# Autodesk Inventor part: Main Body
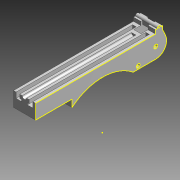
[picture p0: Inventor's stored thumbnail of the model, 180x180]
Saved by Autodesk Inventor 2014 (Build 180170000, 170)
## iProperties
Created: 2013-11
Part Number: Main Body
Material: Generic
Document SubType Name: Modeling
Designer: 603839
Density: 1 g/cm^3
Appearance: Smooth - White
Mass: 205.48 g
Surface Area: 490.982 cm^2
Volume: 205.48 cm^3
Author: 603839
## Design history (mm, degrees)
sketch "Sketch1"
  geometry: L1 (-19.05, 114.3)-(-19.05, -114.3); L2 (-19.05, -114.3)-(19.05, -114.3); L3 (19.05, -114.3)-(19.05, 114.3); L4 (19.05, 114.3)-(-19.05, 114.3); L5 (-19.05, 114.3)-(19.05, -114.3); L6 (-19.05, -114.3)-(19.05, 114.3); 1 further point
  constraints: 12 end point, 2 midpoint, 2 parallel, 1 perpendicular, 1 vertical
  dimensions: "d0" = 228.6 distance of L1.start L1.end; "d1" = 38.1 distance of L2.end L1.end
extrude "Extrusion1" new body sketch "Sketch1" distance "d2" = 38.1; taper "d3" = 0 deg
sketch "Sketch2"
  geometry: L1 (0, 38.1)-(38.1, 38.1) reference; C1 r 3.81 at (19.05, 38.1); 1 further point
  constraints: 1 centre point, 1 midpoint
  dimensions: "d4" = 7.62 diameter of C1
extrude "Extrusion2" cut sketch "Sketch2" distance "d5" = 190.5; taper "d6" = 0 deg
sketch "Sketch3"
  geometry: L1 (114.3, -19.05)-(114.3, 19.05) reference; L2 (114.3, 19.05)-(-114.3, 19.05) reference; L3 (95.25, 19.05)-(95.25, -19.05); L4 (95.25, 19.05)-(133.35, 19.05); L5 (95.25, 19.05)-(114.3, 19.05); L6 (114.3, 0)-(114.3, 19.05); L7 (95.25, -19.05)-(114.3, -19.05); L8 (114.3, -19.05)-(114.3, 0); A1 r 19.05 centre (95.25, 0) between (95.25, -19.05) and (95.25, 19.05); 1 further point
  constraints: 12 end point, 3 point on circle, 2 tangent, 1 centre point, 1 collinear, 1 horizontal, 1 perpendicular, 1 point on line
  dimensions: "d9" = 38.1 distance of L3.start L3.end; "d10" = 90 deg angle of L3 L4
extrude "Extrusion3" cut sketch "Sketch3" distance "d11" = 203.2; taper "d12" = 0 deg
hole "Hole1" diameter "d15" = 6.604; stored, may be unused: countersink angle "d19" = 82 deg, drill point angle "d21" = 0 deg; dims "d16" = 19.05, "d17" = 9.525, "d18" = 6.35, "d20" = 38.1, "d65" = 25.4, "d66" = 25.4
sketch "Sketch4"
  geometry: L1 (-114.3, -19.05)-(95.25, -19.05) reference; L2 (-114.3, -19.05)-(-50.8, -19.05); L3 (95.25, -19.05)-(82.55, -19.05); A1 r 19.05 centre (95.25, 0) between (95.25, -19.05) and (95.25, 19.05) reference; A2 r 126.201 centre (15.875, -126.2) between (82.55, -19.05) and (-50.8, -19.05); 1 further point
  constraints: 4 end point, 3 point on circle, 2 point on line, 1 centre point
  dimensions: "d24" = 63.5 distance of L1.start L2.end; "d25" = 12.7 distance of L3.start L3.end
extrude "Extrusion4" cut sketch "Sketch4" distance "d26" = 203.2; taper "d27" = 0 deg
sketch "Sketch5"
  geometry: L1 (-114.3, 19.05)-(-114.3, -19.05) reference; L2 (-114.3, -19.05)-(-50.8, -19.05) reference; L3 (-114.3, -19.05)-(-114.3, -6.35); L4 (-114.3, -6.35)-(-50.8, -6.35); L5 (-50.8, -6.35)-(-50.8, -19.05); 1 further point
  constraints: 6 end point, 1 parallel, 1 perpendicular, 1 point on line
  dimensions: "d28" = 12.7 distance of L1.end L3.end
extrude "Extrusion5" cut sketch "Sketch5" distance "d29" = 203.2; taper "d30" = 0 deg
workplane "Work Plane1"
sketch "Sketch10"
  geometry: L1 (0, 12.7)-(0, 0) reference; L2 (12.446, 12.7)-(12.446, -25.4); L3 (12.446, -25.4)-(25.146, -25.4); L4 (25.146, -25.4)-(25.146, 12.7); L5 (25.146, 12.7)-(12.446, 12.7); 1 further point
  constraints: 8 end point, 3 parallel, 1 perpendicular
  dimensions: "d47" = 38.1 distance of L2.start L2.end; "d50" = 12.7 distance of L2.end L3.end
extrude "Extrusion8" cut sketch "Sketch10" distance "d48" = 38.1; taper "d49" = 0 deg
sketch "Sketch11"
  geometry: L1 (-2.794, 196.85)-(-2.794, 209.55) reference; L2 (22.86, 209.55)-(22.86, 0) reference; L3 (-15.24, 209.55)-(-2.794, 209.55); L4 (-2.794, 209.55)-(-2.794, 204.476); L5 (-2.794, 204.476)-(-15.24, 204.476); L6 (-15.24, 204.476)-(-15.24, 209.55); L7 (9.906, 209.55)-(22.86, 209.55); L8 (22.86, 209.55)-(22.86, 204.476); L9 (22.86, 204.476)-(9.906, 204.476); L10 (9.906, 204.476)-(9.906, 209.55); 1 further point
  constraints: 16 end point, 4 parallel, 2 horizontal, 2 perpendicular, 2 point on line
extrude "Extrusion9" join sketch "Sketch11" distance "d51" = 12.7; taper "d52" = 0 deg
sketch "Sketch12"
  geometry: L1 (95.25, 19.05)-(95.25, 31.75) reference; A1 r 19.05 centre (95.25, 0) between (95.25, -19.05) and (95.25, 19.05) reference; A2 r 23.785 centre (85.449, 10.078) between (109.035, 13.148) and (95.25, 31.75); 1 further point
  constraints: 3 point on circle, 1 centre point
extrude "Extrusion10" join sketch "Sketch12" distance "d53" = 38.1; taper "d54" = 0 deg
sketch "Sketch13"
  geometry: L1 (12.7, -12.7)-(12.7, 0) reference; L2 (12.7, 0)-(0, 0) reference; L3 (0, -12.7)-(0, 0) reference; L4 (12.7, -12.7)-(0, -12.7) reference; 1 further point
extrude "Extrusion11" cut sketch "Sketch13" distance "d55" = 38.1; taper "d56" = 0 deg
sketch "Sketch14"
  geometry: L1 (0, -12.227)-(12.7, -12.227); L2 (12.7, -12.227)-(12.7, 6.703); L3 (12.7, 6.703)-(0, 6.703); L4 (0, 6.703)-(0, -12.227); 1 further point
  constraints: 8 end point, 2 parallel, 1 horizontal, 1 perpendicular
extrude "Extrusion12" cut sketch "Sketch14" distance "d57" = 38.1; taper "d58" = 0 deg
sketch "Sketch15"
  geometry: L1 (12.7, 0)-(12.7, 38.1) reference; L2 (0, 0)-(0, 38.1) reference; L3 (0, 0)-(0, 6.35); L4 (0, 6.35)-(0, 29.21); L5 (0, 29.21)-(12.7, 29.21); L6 (12.7, 29.21)-(12.7, 6.35); L7 (12.7, 6.35)-(0, 6.35); L8 (0, 6.35)-(0, 29.21); 1 further point
  constraints: 12 end point, 3 point on line, 2 parallel, 1 horizontal, 1 perpendicular
  dimensions: "d59" = 6.35 distance of L2.start L3.end; "d60" = 22.86 distance of L3.end L4.end
extrude "Extrusion13" cut sketch "Sketch15" distance "d61" = 12.7; taper "d62" = 0 deg
sketch "Sketch16"
  geometry: L1 (12.7, -11.499)-(0, -11.499) reference; L2 (12.7, 0)-(12.7, -11.499) reference; L3 (0, 0)-(12.7, 0) reference; L4 (0, 0)-(0, -11.499) reference; 1 further point
extrude "Extrusion14" cut sketch "Sketch16" distance "d63" = 12.7; taper "d64" = 0 deg
hole "Hole2" diameter "d69" = 6.604; stored, may be unused: countersink angle "d73" = 82 deg, drill point angle "d75" = 0 deg; dims "d67" = 7.62, "d68" = 5.08, "d70" = 19.05, "d71" = 9.525, "d72" = 6.35, "d74" = 38.1
sketch "Sketch7"
  geometry: L1 (-19.05, 0)-(-3.81, 0) reference; L2 (-19.05, -25.4)-(19.05, -25.4) reference; L3 (0, 0)-(0, -25.4); L4 (-11.43, 0)-(-8.255, 0); L5 (-11.43, 0)-(-14.605, 0); L6 (-14.605, 0)-(-14.605, -6.35); L7 (-8.255, 0)-(-8.255, -6.35); L8 (-8.255, -9.525)-(-17.78, -9.525); L9 (-17.78, -9.525)-(-17.78, -6.35); L10 (-17.78, -6.35)-(-14.605, -6.35); L11 (8.255, 0)-(8.255, -6.35); L12 (11.43, 0)-(8.255, 0); L13 (17.78, -9.525)-(17.78, -6.35); L14 (8.255, -9.525)-(17.78, -9.525); L15 (17.78, -6.35)-(14.605, -6.35); L16 (14.605, 0)-(14.605, -6.35); L17 (11.43, 0)-(14.605, 0); L18 (-8.255, -6.35)-(-8.255, -9.525); L19 (8.255, -6.35)-(8.255, -9.525); A1 r 3.81 centre (0, 0) between (-3.81, 0) and (3.81, 0) reference; 3 further points
  constraints: 34 end point, 8 symmetric about line, 3 perpendicular, 2 midpoint, 2 point on line, 1 parallel
  dimensions: "d78" = 3.175 distance of L4.start L5.end; "d81" = 12.7 distance of point (-5.08, -9.525) L8.end; "d82" = 3.175 distance of L8.end L9.end
extrude "Extrusion15" cut sketch "Sketch7" distance "d83" = 203.2; taper "d84" = 0 deg
sketch "Sketch17"
  geometry: L1 (90.176, 31.75)-(95.25, 31.75) reference; L2 (90.176, 19.05)-(90.176, 31.75) reference; L3 (-114.3, 19.05)-(-114.3, -6.35) reference; L4 (90.176, 19.05)-(107.477, 19.05); C1 r 3.302 at (95.256, 24.13) reference; A1 r 23.785 centre (85.449, 10.078) between (109.035, 13.148) and (95.25, 31.75) reference; 1 further point
  constraints: 2 end point, 1 perpendicular, 1 point on circle
extrude "Extrusion16" cut sketch "Sketch17" distance "d85" = 203.2; taper "d86" = 0 deg
sketch "Sketch18"
  geometry: L1 (107.477, 19.05)-(-114.3, 19.05) reference; L2 (82.55, -19.05)-(95.25, -19.05) reference; L3 (107.477, 19.05)-(107.477, 31.75); L4 (107.477, 31.75)-(94.777, 31.75); L5 (94.777, 31.75)-(94.777, 19.05); 1 further point
  constraints: 6 end point, 3 perpendicular, 1 point on line
  dimensions: "d87" = 12.7 distance of L1.start L3.end; "d88" = 12.7 distance of L3.end L4.end
extrude "Extrusion17" join sketch "Sketch18" stored distance "d89" = 203.2; taper "d90" = 0 deg
sketch "Sketch19"
  geometry: L1 (-12.954, 0)-(-25.654, 0) reference; L2 (0, 12.7)-(-38.1, 12.7) reference; L3 (-25.654, 0)-(-25.654, 12.7); L4 (-12.954, 0)-(-12.954, 12.7); 1 further point
  constraints: 4 end point, 2 perpendicular, 2 point on line
extrude "Extrusion18" cut sketch "Sketch19" distance "d91" = 203.2; taper "d92" = 0 deg
sketch "Sketch20"
  geometry: L1 (107.477, 19.05)-(107.477, 31.75) reference; L2 (107.477, 31.75)-(94.777, 31.75) reference; L3 (94.777, 31.75)-(94.777, 19.05) reference; L4 (107.477, 19.05)-(112.569, 7.934); L5 (107.477, 19.05)-(107.477, 25.4); L6 (94.777, 25.4)-(107.477, 25.4); A1 r 19.05 centre (95.25, 0) between (95.25, -19.05) and (109.035, 13.148) reference; 1 further point
  constraints: 6 end point, 2 midpoint, 1 perpendicular, 1 point on circle, 1 tangent
extrude "Extrusion19" cut sketch "Sketch20" distance "d93" = 203.2; taper "d94" = 0 deg
sketch "Sketch21"
  geometry: L1 (107.477, 19.05)-(112.569, 7.934); A1 r 19.05 centre (95.25, 0) between (95.25, -19.05) and (109.035, 13.148) reference; A2 r 23.785 centre (85.449, 10.078) between (109.035, 13.148) and (107.477, 19.05) reference; 1 further point
  constraints: 2 end point, 1 point on circle, 1 tangent
extrude "Extrusion20" join sketch "Sketch21" stored distance "d95" = 203.2; taper "d96" = 0 deg
sketch "Sketch22"
  geometry: L1 (12.954, 0)-(25.654, 0); L2 (25.654, 0)-(25.654, -12.227); L3 (25.654, -12.227)-(12.954, -12.227); L4 (12.954, -12.227)-(12.954, 0); 1 further point
  constraints: 8 end point, 2 parallel, 1 horizontal, 1 perpendicular
extrude "Extrusion21" cut sketch "Sketch22" distance "d97" = 2.54; taper "d98" = 0 deg
sketch "Sketch23"
  geometry: L1 (107.477, 25.4)-(94.777, 25.4) reference; C1 r 3.175 at (101.127, 25.4); 1 further point
  constraints: 1 centre point, 1 midpoint
  dimensions: "d99" = 6.35 diameter of C1
extrude "Extrusion22" join sketch "Sketch23" stored distance "d100" = 2.54; taper "d101" = 0 deg
sketch "Sketch25"
  geometry: L1 (94.777, 19.05)-(-114.3, 19.05) reference; L2 (107.477, 25.4)-(104.302, 25.4) reference; L3 (64.328, 19.05)-(64.328, 12.923); L4 (107.477, 19.05)-(107.477, 25.4) reference; L5 (77.028, 10.383)-(64.328, 10.383); L6 (64.328, 10.383)-(64.328, 12.923); C1 r 3.175 at (64.328, 12.923); 1 further point
  constraints: 6 end point, 2 perpendicular, 2 point on line, 1 centre point, 1 coincident
  dimensions: "d105" = 6.35 diameter of C1; "d108" = 12.7 distance of L5.start L5.end; "d109" = 2.54 distance of L5.end L6.end
extrude "Extrusion24" join sketch "Sketch25" distance "d106" = 6.35; taper "d107" = 0 deg
sketch "Sketch26"
  geometry: C1 r 3.175 at (0, 0) reference; 1 further point
extrude "Extrusion25" join sketch "Sketch26" distance "d110" = 12.7; taper "d111" = 0 deg
sketch "Sketch27"
  geometry: L1 (24.927, 44.45)-(21.752, 44.45) reference; L2 (21.752, 44.45)-(21.752, 38.1); L3 (21.752, 38.1)-(15.402, 38.1); L4 (15.402, 38.1)-(15.402, 44.45); A1 r 3.175 centre (18.577, 44.45) between (15.402, 44.45) and (21.752, 44.45) reference; 1 further point
  constraints: 6 end point, 2 perpendicular, 1 tangent
  dimensions: "d112" = 6.35 distance of L1.end L2.end; "d113" = 6.35 distance of L2.end L3.end
extrude "Extrusion26" join sketch "Sketch27" distance "d114" = 25.4; taper "d115" = 0 deg
sketch "Sketch28"
  geometry: L1 (107.477, 25.4)-(104.302, 25.4) reference; L2 (31.75, 0)-(44.45, 0); L3 (44.45, 0)-(44.45, -3.277); L4 (31.75, 0)-(31.75, -1.002); A1 r 126.201 centre (15.875, -126.2) between (82.55, -19.05) and (-50.8, -19.05) reference; A2 r 126.201 centre (15.875, -126.2) between (44.45, -3.277) and (31.75, -1.002); 1 further point
  constraints: 6 end point, 4 point on circle, 2 parallel, 1 centre point, 1 concentric, 1 perpendicular
  dimensions: "d116" = 12.7 distance of L2.start L2.end
extrude "Extrusion27" join sketch "Sketch28" distance "d117" = 12.7; taper "d118" = 0 deg
sketch "Sketch29"
  geometry: L1 (44.45, 0)-(31.75, 0) reference; L2 (31.75, 0)-(31.75, -6.35); L3 (31.75, -6.35)-(44.45, -6.35); L4 (44.45, -6.35)-(44.45, 0); 1 further point
  constraints: 6 end point, 2 perpendicular
  dimensions: "d119" = 6.35 distance of L1.end L2.end; "d120" = 12.7 distance of L2.end L3.end
extrude "Extrusion28" join sketch "Sketch29" stored distance "d121" = 12.7; taper "d122" = 0 deg
sketch "Sketch30"
  geometry: L1 (-44.45, -3.277)-(-44.45, -6.35) reference; L2 (-44.45, -6.35)-(-31.75, -6.35) reference; L3 (-44.45, -3.277)-(-44.45, -6.35); L4 (-31.75, -6.35)-(-44.45, -6.35); A1 r 126.201 centre (-15.875, -126.2) between (-44.45, -3.277) and (-82.55, -19.05) reference; A2 r 107.95 centre (-31.75, -114.3) between (-31.75, -6.35) and (-82.55, -19.05); A3 r 126.201 centre (-15.875, -126.2) between (-44.45, -3.277) and (-82.55, -19.05); 1 further point
  constraints: 4 end point, 4 point on circle, 2 centre point, 2 collinear, 2 tangent, 1 concentric
extrude "Extrusion29" join sketch "Sketch30" stored distance "d123" = 12.7; taper "d124" = 0 deg
sketch "Sketch31"
  geometry: L1 (-31.75, -6.35)-(-31.75, -1.002) reference; A1 r 126.201 centre (-15.875, -126.2) between (50.8, -19.05) and (-31.75, -1.002) reference; A2 r 267.228 centre (-30.61, -273.576) between (50.8, -19.05) and (-31.75, -6.35); 1 further point
  constraints: 2 point on circle, 1 centre point
extrude "Extrusion30" join sketch "Sketch31" stored distance "d125" = 12.7; taper "d126" = 0 deg
sketch "Sketch33"
  geometry: L1 (44.45, -6.35)-(44.45, 0) reference; L2 (44.45, 0)-(31.75, 0) reference; L3 (44.45, -3.175)-(31.75, 0); 1 further point
  constraints: 2 end point, 1 midpoint
extrude "Extrusion32" cut sketch "Sketch33" stored distance "d133" = 3.175; taper "d134" = 0 deg
sketch "Sketch34"
  geometry: C1 r 5.715 at (6.35, 6.545); 1 further point
  constraints: 1 centre point
  dimensions: "d135" = 11.43 diameter of C1
extrude "Extrusion33" cut sketch "Sketch34" distance "d136" = 3.175; taper "d137" = 0 deg
sketch "Sketch36"
  geometry: L1 (31.75, -6.35)-(44.45, -6.35) reference; L2 (31.75, -6.35)-(31.75, 0) reference; L3 (31.75, -6.35)-(44.45, -6.35); L4 (44.45, -6.35)-(44.45, -7.1); A1 r 107.95 centre (31.75, -114.3) between (82.55, -19.05) and (31.75, -6.35) reference; A2 r 107.95 centre (31.75, -114.3) between (44.45, -7.1) and (31.75, -6.35); 1 further point
  constraints: 4 end point, 3 point on circle, 2 perpendicular, 1 centre point, 1 concentric, 1 tangent
extrude "Extrusion34" join sketch "Sketch36" stored distance "d138" = 25.4; taper "d139" = 0 deg
sketch "Sketch37"
  geometry: L1 (44.45, -3.175)-(44.45, -7.1) reference; L2 (31.75, -6.35)-(31.75, 0) reference; L3 (44.45, -3.175)-(31.75, 0) reference; L4 (-50.8, -19.05)-(82.55, -19.05); A1 r 107.95 centre (31.75, -114.3) between (82.55, -19.05) and (44.45, -7.1) reference; A2 r 267.228 centre (30.61, -273.576) between (31.75, -6.35) and (-50.8, -19.05) reference; 1 further point
  constraints: 2 end point, 1 perpendicular
extrude "Extrusion35" join sketch "Sketch37" stored distance "d140" = 25.4; taper "d141" = 0 deg
sketch "Sketch38"
  geometry: L1 (44.45, -3.175)-(31.75, 0) reference; L2 (31.75, 0)-(31.75, -6.35) reference; L3 (44.45, -7.1)-(44.45, -3.175) reference; A1 r 107.95 centre (31.75, -114.3) between (44.45, -7.1) and (31.75, -6.35) reference; 1 further point
extrude "Extrusion36" cut sketch "Sketch38" stored distance "d142" = 25.4; taper "d143" = 0 deg
sketch "Sketch39"
  geometry: C1 r 3.175 at (0, 0) reference; 1 further point
extrude "Extrusion37" cut sketch "Sketch39" stored distance "d144" = 25.4; taper "d145" = 0 deg
sketch "Sketch40"
  geometry: L1 (-50.8, -19.05)-(95.25, -19.05) reference; L2 (-50.8, -6.35)-(-50.8, -19.05) reference; C1 r 3.302 at (64.77, -13.97); 1 further point
  constraints: 1 centre point
  dimensions: "d146" = 6.604 diameter of C1; "d147" = 5.08 distance from line of L1 C1.centre; "d148" = 115.57 distance from line of L2 C1.centre
extrude "Extrusion38" cut sketch "Sketch40" distance "d149" = 25.4; taper "d150" = 0 deg
sketch "Sketch41"
  geometry: L1 (-50.8, -19.05)-(95.25, -19.05) reference; A1 r 84.07 centre (2.54, -84.032) between (55.88, -19.05) and (-50.8, -19.05); 1 further point
  constraints: 3 point on circle, 1 centre point, 1 point on line
  dimensions: "d151" = 106.68 distance of L1.start A1.start
extrude "Extrusion39" cut sketch "Sketch41" stored distance "d152" = 25.4; taper "d153" = 0 deg
sketch "Sketch42"
  geometry: L1 (8.255, -9.525)-(8.255, 0) reference; L2 (-8.255, 0)-(-8.255, -9.525) reference; L3 (-17.78, -6.35)-(-14.605, -6.35) reference; L4 (-8.255, -6.35)-(-5.08, -6.35); L5 (-5.08, -6.35)-(-5.08, -9.525); L6 (-5.08, -9.525)-(-8.255, -9.525); L7 (8.255, -9.525)-(5.08, -9.525); L8 (5.08, -9.525)-(5.08, -6.35); L9 (5.08, -6.35)-(8.255, -6.35); 1 further point
  constraints: 12 end point, 3 equal length, 3 perpendicular, 2 point on line
  dimensions: "d154" = 3.175 distance of L4.start L4.end; "d155" = 3.175 distance of L4.end L5.end; "d156" = 3.175 distance of L1.start L7.end; "d157" = 3.175 distance of L7.end L8.end
extrude "Extrusion40" cut sketch "Sketch42" stored distance "d158" = 25.4; taper "d159" = 0 deg
sketch "Sketch43"
  geometry: L1 (-5.08, -9.525)-(-17.78, -9.525) reference; L2 (-17.78, -9.525)-(-17.78, -6.35) reference; L3 (-17.78, -6.35)-(-14.605, -6.35) reference; L4 (14.605, -6.35)-(17.78, -6.35) reference; L5 (17.78, -6.35)-(17.78, -9.525) reference; L6 (17.78, -9.525)-(5.08, -9.525) reference; L7 (-14.605, -6.35)-(-14.605, -9.525); L8 (14.605, -6.35)-(14.605, -9.525); 1 further point
  constraints: 4 end point, 2 perpendicular, 2 point on line
extrude "Extrusion41" join sketch "Sketch43" stored distance "d160" = 25.4; taper "d161" = 0 deg
sketch "Sketch46"
  geometry: L1 (12.7, 3.175)-(19.05, 3.175) reference; L2 (19.05, 3.175)-(19.05, 0) reference; L3 (19.05, 0)-(0, 0) reference; L4 (0, 0)-(0, -21.649) reference; L5 (25.4, -28.575)-(12.7, -28.575) reference; L6 (37.627, 9.525)-(42.719, -1.591) reference; L7 (37.627, 15.875)-(37.627, 9.525) reference; L8 (37.627, 15.875)-(34.452, 15.875) reference; L9 (34.452, 15.875)-(34.452, 9.525) reference; L10 (34.452, 9.525)-(28.102, 9.525) reference; L11 (28.102, 9.525)-(28.102, 15.875) reference; L12 (28.102, 15.875)-(24.927, 15.875) reference; L13 (24.927, 9.525)-(24.927, 15.875) reference; L14 (12.7, 9.525)-(24.927, 9.525) reference; L15 (12.7, 3.175)-(12.7, 9.525) reference; C1 r 3.302 at (25.4, -9.525) reference; A1 r 126.201 centre (-53.975, -135.725) between (12.7, -28.575) and (0, -21.649) reference; A2 r 19.05 centre (25.4, -9.525) between (25.4, -28.575) and (42.719, -1.591) reference; 1 further point
extrude "Extrusion44" join sketch "Sketch46" distance "d166" = 0.254; taper "d167" = 0 deg
sketch "Sketch47"
  geometry: L1 (0, 3.175)-(6.35, 3.175) reference; L2 (6.35, 3.175)-(6.35, 9.525) reference; L3 (-5.877, 9.525)-(6.35, 9.525) reference; L4 (-5.877, 15.875)-(-5.877, 9.525) reference; L5 (-5.877, 15.875)-(-9.052, 15.875) reference; L6 (-9.052, 15.875)-(-9.052, 9.525) reference; L7 (-9.052, 9.525)-(-15.402, 9.525) reference; L8 (-15.402, 9.525)-(-15.402, 15.875) reference; L9 (-15.402, 15.875)-(-18.577, 15.875) reference; L10 (-18.577, 9.525)-(-18.577, 15.875) reference; L11 (-23.669, -1.591)-(-18.577, 9.525) reference; L12 (6.35, -28.575)-(-6.35, -28.575) reference; L13 (19.05, -21.649)-(19.05, 0) reference; L14 (19.05, 0)-(0, 0) reference; L15 (0, 0)-(0, 3.175) reference; C1 r 3.302 at (-6.35, -9.525) reference; A1 r 19.05 centre (-6.35, -9.525) between (-23.669, -1.591) and (-6.35, -28.575) reference; A2 r 126.201 centre (73.025, -135.725) between (19.05, -21.649) and (6.35, -28.575) reference; 1 further point
extrude "Extrusion45" cut sketch "Sketch47" distance "d168" = 0.254; taper "d169" = 0 deg
sketch "Sketch51"
  geometry: L1 (55.88, -19.05)-(95.25, -19.05) reference; L2 (112.569, 7.934)-(107.477, 19.05) reference; L3 (107.477, 19.05)-(107.477, 25.4) reference; L4 (107.477, 25.4)-(104.302, 25.4) reference; L5 (97.952, 25.4)-(94.777, 25.4) reference; L6 (94.777, 25.4)-(94.777, 19.05) reference; L7 (94.777, 19.05)-(-114.3, 19.05) reference; L8 (-114.3, 19.05)-(-114.3, -6.35) reference; L9 (-114.3, -6.35)-(-50.8, -6.35) reference; L10 (-50.8, -6.35)-(-50.8, -19.05) reference; C1 r 3.302 at (95.25, 0) reference; C2 r 3.302 at (64.77, -13.97) reference; A1 r 84.07 centre (2.54, -84.032) between (55.88, -19.05) and (-50.8, -19.05) reference; A2 r 19.05 centre (95.25, 0) between (95.25, -19.05) and (112.569, 7.934) reference; A3 r 3.175 centre (101.127, 25.4) between (104.302, 25.4) and (97.952, 25.4) reference; 1 further point
sketch "Sketch52"
  geometry: L1 (94.777, 19.05)-(-114.3, 19.05) reference; L2 (-50.8, -6.35)-(-50.8, -19.05) reference; L3 (51.233, 19.05)-(51.233, 8.89); L4 (51.233, 8.89)-(72.103, 19.05); L5 (51.233, 19.05)-(72.103, 19.05); 1 further point
  constraints: 6 end point, 2 point on line, 1 collinear, 1 parallel
  dimensions: "d190" = 10.16 distance of L3.start L3.end
extrude "Extrusion48" join sketch "Sketch52" distance "d191" = 12.7; taper "d192" = 0 deg
sketch "Sketch53"
  geometry: C1 r 4.445 at (6.35, 11.606); 1 further point
  constraints: 1 centre point
  dimensions: "d193" = 8.89 diameter of C1
extrude "Extrusion49" join sketch "Sketch53" distance "d194" = 4.445; taper "d195" = 0 deg
body "Solid1"
other parameters: "d41" = 25.4
